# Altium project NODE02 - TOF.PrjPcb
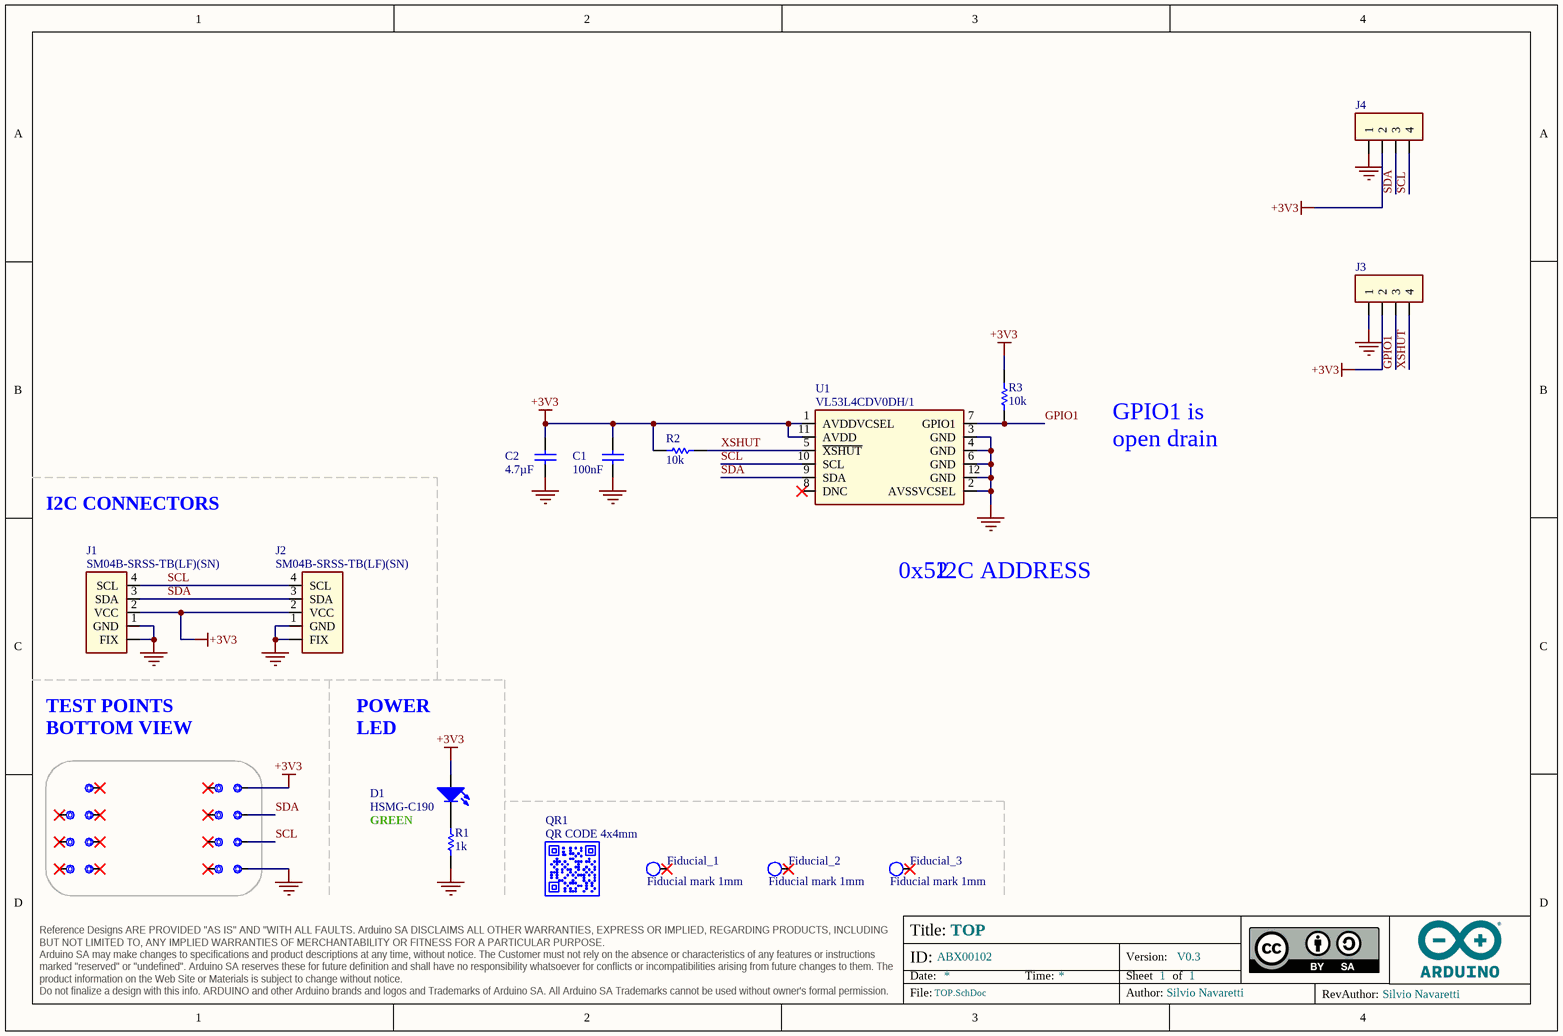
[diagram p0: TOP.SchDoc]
ASSEMBLY_BGA: _; ASSEMBLY_PRESSFIT: _; ASSEMBLY_SMD: X; ASSEMBLY_THT: _; BOARD_CODENAME: NODE02; BOARD_INFO_AUTHOR: Silvio Navaretti; BOARD_INFO_AUTHOR_REV: Silvio Navaretti; BOARD_INFO_Er: _; BOARD_INFO_FLEX: _; BOARD_INFO_FR4: X; BOARD_INFO_FR4_HTG: _; BOARD_INFO_IPC1: _; BOARD_INFO_IPC2: X; BOARD_INFO_IPC3: _; BOARD_INFO_IPC_NA: _; BOARD_INFO_NUMBER_OF_LAYERS: 2; BOARD_INFO_PCB_SIZE: 41.00x25.36mm; BOARD_INFO_POLYMIDE: _; BOARD_INFO_RIGID: X; BOARD_INFO_RIGID/FLEX: _; BOARD_INFO_TBD: _; BOARD_INFO_THICKNESS: 1.6mm; DRILLS_BLIND: _; DRILLS_BURIED: _; DRILLS_COPPER_FILLING: _; DRILLS_FULL: X; DRILLS_LASER: _; DRILLS_PRESSFIT: _; DRILLS_RESIN_FILLING: _; DRILLS_SLOT: _; DRILLS_SOLDER_FILLING: X; FINISH_ADJUSTMENTS: _; FINISH_EDGE_PLATING: _; FINISH_ENIG: _; FINISH_HAL: _; FINISH_HAL_LF: X; FINISH_NI/AU: _; FINISH_SILK_BOTTOM: X; FINISH_SILK_COLOR: WHITE; FINISH_SILK_TOP: X; FINISH_SN/PB: _; FINISH_SOLDERMASK_BOTTOM: X; FINISH_SOLDERMASK_COLOR: BLUE; FINISH_SOLDERMASK_PEELABLE_BOTTOM: _; FINISH_SOLDERMASK_PEELABLE_COLOR: _; FINISH_SOLDERMASK_PEELABLE_TOP: _; FINISH_SOLDERMASK_TOP: X; FINISH_TABS: _; FINISH_TBD: _; INSULATION_MIN_INNER: 0.15mm; INSULATION_MIN_OUTER: 0.15mm; PANEL_MILLING: X; PANEL_NOT_REQUESTED: _; PANEL_NUMBER_OF_FIGURES: 30; PANEL_PROVIDED: X; PANEL_REQUESTED: _; PANEL_SCORING: X; PANEL_SIZE: 262x221mm; PANEL_TABS: _; SKU: ABX00102; TRACK_MIN_WIDTH_INNER: 0.15mm; TRACK_MIN_WIDTH_OUTER: 0.15mm; Version: V0.3; VIA_1: _; VIA_1_HOLE_MM: _; VIA_1_PAD_MM: _; VIA_2: _; VIA_2_HOLE_MM: _; VIA_2_PAD_MM: _; VIA_3: _; VIA_3_HOLE_MM: _; VIA_3_PAD_MM: _; VIA_4: _; VIA_4_HOLE_MM: _; VIA_4_PAD_MM: _; VIA_5: _; VIA_5_HOLE_MM: _; VIA_5_PAD_MM: _; VIA_THROUGH: X; VIA_THROUGH_HOLE_MM: 0.3; VIA_THROUGH_PAD_MM: 0.6
1 sheet, 30 parts. Net scope: hierarchical (ports join the sheet entries above them; power ports are global).
Board file: PCB.PcbDoc

## Sheet TOP.SchDoc: TOP
size A4; Revision: V0.3; SheetNumber: 1; SheetTotal: 1

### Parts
3V3  Test point 1.00mm  [TP-1.00MM]  (value not drawn)  (no BOM)
C1  value 100nF  [CAP-0402]  (hidden comment: 0402B104K160CT)
C2  value 4.7µF  [CAP-0603]  (hidden comment: GRM188R61C475KAAJD)
D1  HSMG-C190  [LEDC1608X80N-AK]
Fiducial_1  Fiducial mark 1mm  [Fiducial mark 1mm-Footprint-1]  (no BOM)
Fiducial_2  Fiducial mark 1mm  [Fiducial mark 1mm-Footprint-1]  (no BOM)
Fiducial_3  Fiducial mark 1mm  [Fiducial mark 1mm-Footprint-1]  (no BOM)
GND  Test point 1.00mm  [TP-1.00MM]  (value not drawn)  (no BOM)
J1  SM04B-SRSS-TB(LF)(SN)  [SM04B-SRSS-TB(LF)(SN)-Footprint-1]
J2  SM04B-SRSS-TB(LF)(SN)  [SM04B-SRSS-TB(LF)(SN)-Footprint-1]
J3  HEADER TH 2.54mm VERT. 1x004POS  [PIN HEADER 2.54mm VERT. 1x4POS-Footprint-1]  (value not drawn)  (no BOM)
J4  HEADER TH 2.54mm VERT. 1x004POS  [PIN HEADER 2.54mm VERT. 1x4POS-Footprint-1]  (value not drawn)  (no BOM)
NRST  Test point 1.00mm  [TP-1.00MM]  (value not drawn)  (no BOM)
PA6  Test point 1.00mm  [TP-1.00MM]  (value not drawn)  (no BOM)
PA7  Test point 1.00mm  [TP-1.00MM]  (value not drawn)  (no BOM)
PC14  Test point 1.00mm  [TP-1.00MM]  (value not drawn)  (no BOM)
PC15  Test point 1.00mm  [TP-1.00MM]  (value not drawn)  (no BOM)
QR1  QR CODE 4x4mm  [QR CODE 4x4mm]  (no BOM)
R1  value 1k  [RES-0402]  (hidden comment: CRCW04021K00FKEDC)
R2  value 10k  [RES-0402]  (hidden comment: CRCW040210K0FKED)
R3  value 10k  [RES-0402]  (hidden comment: CRCW040210K0FKED)
SCL  Test point 1.00mm  [TP-1.00MM]  (value not drawn)  (no BOM)
SDA  Test point 1.00mm  [TP-1.00MM]  (value not drawn)  (no BOM)
SWCLK  Test point 1.00mm  [TP-1.00MM]  (value not drawn)  (no BOM)
SWDIO  Test point 1.00mm  [TP-1.00MM]  (value not drawn)  (no BOM)
TP9  Test point 1.00mm  [TP-1.00MM]  (value not drawn)  (no BOM)
TP10  Test point 1.00mm  [TP-1.00MM]  (value not drawn)  (no BOM)
TP11  Test point 1.00mm  [TP-1.00MM]  (value not drawn)  (no BOM)
TP12  Test point 1.00mm  [TP-1.00MM]  (value not drawn)  (no BOM)
U1  VL53L4CDV0DH/1  [VL53L4CDV0DH/1]

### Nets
+3V3: 3V3.X C1.1 C2.2 D1.A J1.2(VCC) J2.2(VCC) J3.2 J4.2 R2.1 R3.2 U1.1(AVDDVCSEL) U1.11(AVDD)
GND: C1.2 C2.1 GND.X J1.1(GND) J1.FIX J2.1(GND) J2.FIX J3.1 J4.1 R1.1 U1.2(AVSSVCSEL) U1.3(GND) U1.4(GND) U1.6(GND) U1.12(GND)
GPIO1: J3.3 R3.1 U1.7(GPIO1)  [project net GPIO1_1]
SCL: J1.4(SCL) J2.4(SCL) J4.4 SCL.X U1.10(SCL)  [project net SCL_1]
SDA: J1.3(SDA) J2.3(SDA) J4.3 SDA.X U1.9(SDA)  [project net SDA_1]
XSHUT: J3.4 R2.2 U1.5(~{XSHUT})  [project net XSHUT_1]
NetD1_C: D1.C R1.2

Not connected (* = marked no-connect by the designer): Fiducial_1 1*; Fiducial_2 1*; Fiducial_3 1*; NRST X*; PA6 X*; PA7 X*; PC14 X*; PC15 X*; SWCLK X*; SWDIO X*; TP9 X*; TP10 X*; TP11 X*; TP12 X*; U1 8(DNC)*

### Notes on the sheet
- I2C CONNECTORS
- GPIO1 is open drain
- I2C ADDRESS
- 0x52
- TEST POINTS BOTTOM VIEW
- (near D1) POWER LED
- GREEN

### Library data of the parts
3V3 GND NRST PA6 PA7 PC14 PC15 SCL SDA SWCLK SWDIO TP9-TP12 = UT0013-A.6: Manufacturer: This is not a component
C1 = C0012-A.15: CAP CHIP 0402 100nF 10% 16V X7R; Manufacturer: Walsin; Code Arduino: 0132
C2 = C0054-A.16: CAP CHIP 0603 4.7uF 10% 16V X5R; Manufacturer: Murata; Code Arduino: A5072
D1 = L0009-A.5: LED SMD 0603 GREEN/568 15mcd 120^; Manufacturer: Broadcom; Code Arduino: 2204
Fiducial_1-Fiducial_3 = UT0023-A.7: Fiducial mark 1mm clearance 2mm
J1 J2 = J0005-A.2: CONN JST 4POS SIDE 1MM TIN QWIIC; Code Arduino: J0005
J3 J4 = J0162-A.5: Code Arduino: J0162
QR1 = QR-0001-A.2: QR CODE 4x4mm on layer 34 (This is not a component); Code Arduino: QRCODE_4x4mm
R1 = R0007-A.24: RES CHIP 0402 1k 1% 1/16W; Manufacturer: Vishay; Code Arduino: 0140; Power: 62.5mW; Temperature coefficient: 100ppm
R2 R3 = R0003-A.24: RES CHIP 0402 10k 1% 1/16W; Manufacturer: Vishay; Code Arduino: 0136; Power: 62.5mW; Temperature coefficient: 100ppm
U1 = U0380-A.2: SENSOR TOF, 940nm, single supply 2.6V to 3.5V, I2C, 0 to 1300mm, FOV 18°, LGA12 4.4x2.4x1mm; Manufacturer: ST Microelectronics; Code Arduino: U0380

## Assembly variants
ABX00102: all parts fitted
